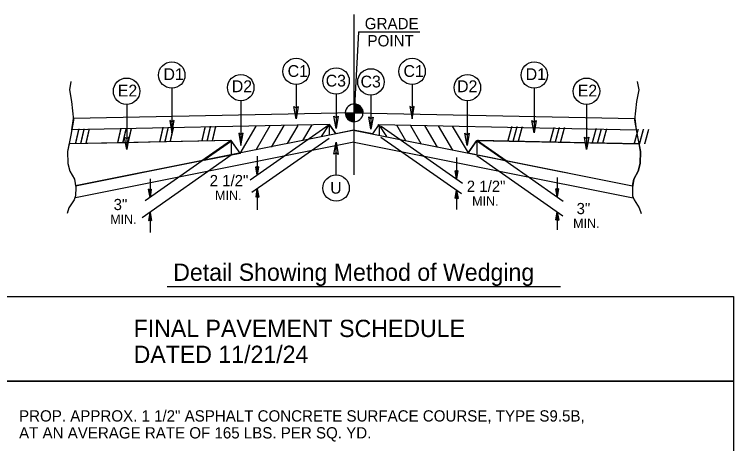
# Model space of a CAD drawing. Extents: x 1901984 to 1902132, y 194049 to 194156.
# Drawn here: x 1902088.64 to 1902130.25, y 194104.06 to 194128.91 of the extents above; entities that cross this region are included whole.
import ezdxf

# ---------------------------------------------------------------- set-up
doc = ezdxf.new("R2010")
doc.units = 0
for name, color, linetype in [('Old_Level_1', 7, 'Continuous'), ('Old_Level_11', 7, 'Continuous'), ('Old_Level_19', 7, 'Continuous'), ('Old_Level_20', 7, 'Continuous'), ('Old_Level_21', 7, 'Continuous'), ('Old_Level_3', 7, 'Continuous')]:
    doc.layers.add(name, color=color, linetype=linetype)

msp = doc.modelspace()

# ---------------------------------------------------------------- linework, layer by layer
at = {"layer": 'Old_Level_1'}
for p, q in [((1902108.298, 194123.202), (1902108.298, 194123.713)), ((1902107.786, 194123.202), (1902108.298, 194123.202)), ((1902108.294, 194122.691), (1902108.294, 194123.196)), ((1902108.298, 194123.202), (1902108.298, 194122.691)), ((1902108.81, 194123.202), (1902108.298, 194123.202)), ((1902108.298, 194122.691), (1902108.298, 194123.202)), ((1902102.612, 194122.439), (1902101.689, 194120.857)), ((1902106.851, 194122.512), (1902102.277, 194119.308)), ((1902103.422, 194122.455), (1902102.605, 194121.053)), ((1902104.224, 194122.471), (1902103.491, 194121.214)), ((1902105.032, 194122.469), (1902104.425, 194121.429)), ((1902105.847, 194122.511), (1902105.317, 194121.603)), ((1902109.855, 194122.437), (1902114.567, 194119.137)), ((1902110.742, 194122.511), (1902111.272, 194121.603)), ((1902111.556, 194122.469), (1902112.164, 194121.429)), ((1902112.365, 194122.471), (1902113.098, 194121.214)), ((1902113.167, 194122.455), (1902113.984, 194121.053)), ((1902113.978, 194122.439), (1902114.886, 194120.881)), ((1902106.862, 194121.729), (1902102.385, 194118.595)), ((1902109.848, 194121.795), (1902114.515, 194118.528)), ((1902101.192, 194121.596), (1902091.808, 194121.408)), ((1902108.288, 194121.51), (1902092.175, 194118.287)), ((1902101.192, 194121.596), (1902096.209, 194118.107)), ((1902101.702, 194120.879), (1902101.192, 194121.596)), ((1902101.192, 194121.596), (1902101.192, 194120.777)), ((1902108.3, 194121.51), (1902124.451, 194118.279)), ((1902114.888, 194120.881), (1902115.397, 194121.596)), ((1902115.397, 194121.596), (1902124.781, 194121.408)), ((1902115.397, 194121.596), (1902115.397, 194120.835)), ((1902115.397, 194121.596), (1902120.387, 194118.102)), ((1902114.886, 194120.881), (1902117.032, 194120.451)), ((1902099.558, 194120.451), (1902092.18, 194118.976)), ((1902101.188, 194120.752), (1902096.037, 194117.127)), ((1902101.192, 194120.779), (1902099.558, 194120.451)), ((1902102.693, 194120.688), (1902102.693, 194119.6)), ((1902114.223, 194120.626), (1902114.223, 194119.378)), ((1902115.397, 194120.736), (1902120.379, 194117.246)), ((1902102.693, 194119.6), (1902102.609, 194120.077)), ((1902102.693, 194120.015), (1902102.609, 194120.077)), ((1902102.693, 194119.6), (1902102.621, 194120.068)), ((1902102.633, 194120.059), (1902102.693, 194119.6)), ((1902102.693, 194119.6), (1902102.645, 194120.051)), ((1902102.658, 194120.042), (1902102.693, 194119.6)), ((1902102.693, 194119.6), (1902102.67, 194120.033)), ((1902102.693, 194119.6), (1902102.778, 194120.077)), ((1902102.778, 194120.077), (1902102.693, 194120.015)), ((1902102.766, 194120.068), (1902102.693, 194119.6)), ((1902102.693, 194119.6), (1902102.753, 194120.059)), ((1902102.741, 194120.051), (1902102.693, 194119.6)), ((1902102.693, 194119.6), (1902102.729, 194120.042)), ((1902102.717, 194120.033), (1902102.693, 194119.6)), ((1902102.682, 194120.024), (1902102.693, 194119.6)), ((1902102.693, 194119.6), (1902102.705, 194120.024)), ((1902102.693, 194120.015), (1902102.693, 194119.6)), ((1902114.223, 194119.378), (1902114.139, 194119.856)), ((1902114.223, 194119.794), (1902114.139, 194119.856)), ((1902114.223, 194119.378), (1902114.151, 194119.847)), ((1902114.163, 194119.838), (1902114.223, 194119.378)), ((1902114.223, 194119.378), (1902114.175, 194119.829)), ((1902114.187, 194119.82), (1902114.223, 194119.378)), ((1902114.223, 194119.378), (1902114.199, 194119.812)), ((1902114.211, 194119.803), (1902114.223, 194119.378)), ((1902114.223, 194119.378), (1902114.308, 194119.856)), ((1902114.308, 194119.856), (1902114.223, 194119.794)), ((1902114.295, 194119.847), (1902114.223, 194119.378)), ((1902114.223, 194119.378), (1902114.283, 194119.838)), ((1902114.271, 194119.829), (1902114.223, 194119.378)), ((1902114.223, 194119.378), (1902114.259, 194119.82)), ((1902114.247, 194119.812), (1902114.223, 194119.378)), ((1902114.223, 194119.378), (1902114.236, 194119.803)), ((1902114.223, 194119.794), (1902114.223, 194119.378)), ((1902096.49, 194119.388), (1902096.49, 194118.303)), ((1902120.049, 194119.467), (1902120.049, 194118.339)), ((1902102.693, 194118.81), (1902102.609, 194118.333)), ((1902102.621, 194118.342), (1902102.693, 194118.81)), ((1902102.693, 194118.81), (1902102.633, 194118.35)), ((1902102.645, 194118.36), (1902102.693, 194118.81)), ((1902102.693, 194118.81), (1902102.658, 194118.368)), ((1902102.67, 194118.377), (1902102.693, 194118.81)), ((1902102.693, 194118.81), (1902102.682, 194118.386)), ((1902102.693, 194118.81), (1902102.693, 194117.585)), ((1902102.693, 194118.81), (1902102.778, 194118.333)), ((1902102.693, 194118.395), (1902102.693, 194118.81)), ((1902102.705, 194118.386), (1902102.693, 194118.81)), ((1902102.693, 194118.81), (1902102.717, 194118.377)), ((1902102.729, 194118.368), (1902102.693, 194118.81)), ((1902102.693, 194118.81), (1902102.741, 194118.36)), ((1902102.753, 194118.35), (1902102.693, 194118.81)), ((1902102.693, 194118.81), (1902102.766, 194118.342)), ((1902120.049, 194118.339), (1902119.965, 194118.816)), ((1902120.049, 194118.754), (1902119.965, 194118.816)), ((1902120.049, 194118.339), (1902119.977, 194118.807)), ((1902119.989, 194118.798), (1902120.049, 194118.339)), ((1902120.049, 194118.339), (1902120.001, 194118.79)), ((1902120.049, 194118.339), (1902120.133, 194118.816)), ((1902120.133, 194118.816), (1902120.049, 194118.754)), ((1902120.121, 194118.807), (1902120.049, 194118.339)), ((1902120.049, 194118.339), (1902120.109, 194118.798)), ((1902120.097, 194118.79), (1902120.049, 194118.339)), ((1902096.49, 194118.303), (1902096.405, 194118.78)), ((1902096.49, 194118.719), (1902096.405, 194118.78)), ((1902096.49, 194118.303), (1902096.417, 194118.772)), ((1902096.43, 194118.762), (1902096.49, 194118.303)), ((1902096.49, 194118.303), (1902096.442, 194118.754)), ((1902096.454, 194118.745), (1902096.49, 194118.303)), ((1902096.49, 194118.303), (1902096.466, 194118.737)), ((1902096.478, 194118.728), (1902096.49, 194118.303)), ((1902096.49, 194118.303), (1902096.574, 194118.78)), ((1902096.574, 194118.78), (1902096.49, 194118.719)), ((1902096.562, 194118.772), (1902096.49, 194118.303)), ((1902096.49, 194118.303), (1902096.55, 194118.762)), ((1902096.538, 194118.754), (1902096.49, 194118.303)), ((1902096.49, 194118.303), (1902096.525, 194118.745)), ((1902096.514, 194118.737), (1902096.49, 194118.303)), ((1902096.49, 194118.303), (1902096.502, 194118.728)), ((1902096.49, 194118.719), (1902096.49, 194118.303)), ((1902102.609, 194118.333), (1902102.693, 194118.395)), ((1902102.693, 194118.395), (1902102.778, 194118.333)), ((1902114.223, 194118.732), (1902114.139, 194118.255)), ((1902114.151, 194118.265), (1902114.223, 194118.732)), ((1902114.223, 194118.732), (1902114.163, 194118.273)), ((1902114.175, 194118.282), (1902114.223, 194118.732)), ((1902114.223, 194118.732), (1902114.187, 194118.291)), ((1902114.199, 194118.299), (1902114.223, 194118.732)), ((1902114.223, 194118.732), (1902114.211, 194118.308)), ((1902114.223, 194118.732), (1902114.223, 194117.616)), ((1902114.223, 194118.732), (1902114.308, 194118.255)), ((1902114.223, 194118.317), (1902114.223, 194118.732)), ((1902114.236, 194118.308), (1902114.223, 194118.732)), ((1902114.223, 194118.732), (1902114.247, 194118.299)), ((1902114.259, 194118.291), (1902114.223, 194118.732)), ((1902114.223, 194118.732), (1902114.271, 194118.282)), ((1902114.283, 194118.273), (1902114.223, 194118.732)), ((1902114.223, 194118.732), (1902114.295, 194118.265)), ((1902120.013, 194118.78), (1902120.049, 194118.339)), ((1902120.049, 194118.339), (1902120.025, 194118.772)), ((1902120.037, 194118.762), (1902120.049, 194118.339)), ((1902120.049, 194118.339), (1902120.085, 194118.78)), ((1902120.073, 194118.772), (1902120.049, 194118.339)), ((1902120.049, 194118.339), (1902120.061, 194118.762)), ((1902120.049, 194118.754), (1902120.049, 194118.339)), ((1902114.139, 194118.255), (1902114.223, 194118.317)), ((1902114.223, 194118.317), (1902114.308, 194118.255)), ((1902096.49, 194117.445), (1902096.405, 194116.967)), ((1902096.418, 194116.976), (1902096.49, 194117.445)), ((1902096.49, 194117.445), (1902096.43, 194116.985)), ((1902096.442, 194116.994), (1902096.49, 194117.445)), ((1902096.49, 194117.445), (1902096.454, 194117.003)), ((1902096.466, 194117.011), (1902096.49, 194117.445)), ((1902096.49, 194117.445), (1902096.478, 194117.02)), ((1902096.49, 194117.445), (1902096.49, 194116.284)), ((1902096.49, 194117.445), (1902096.574, 194116.967)), ((1902096.49, 194117.029), (1902096.49, 194117.445)), ((1902096.502, 194117.02), (1902096.49, 194117.445)), ((1902096.49, 194117.445), (1902096.514, 194117.011)), ((1902096.526, 194117.003), (1902096.49, 194117.445)), ((1902096.49, 194117.445), (1902096.538, 194116.994)), ((1902096.55, 194116.985), (1902096.49, 194117.445)), ((1902096.49, 194117.445), (1902096.562, 194116.976)), ((1902120.049, 194117.478), (1902119.965, 194117)), ((1902119.977, 194117.009), (1902120.049, 194117.478)), ((1902120.049, 194117.478), (1902119.989, 194117.018)), ((1902120.001, 194117.027), (1902120.049, 194117.478)), ((1902120.049, 194117.478), (1902120.013, 194117.036)), ((1902120.025, 194117.045), (1902120.049, 194117.478)), ((1902120.049, 194117.478), (1902120.037, 194117.053)), ((1902120.049, 194117.478), (1902120.049, 194116.43)), ((1902120.049, 194117.478), (1902120.133, 194117)), ((1902120.049, 194117.063), (1902120.049, 194117.478)), ((1902120.061, 194117.053), (1902120.049, 194117.478)), ((1902120.049, 194117.478), (1902120.073, 194117.045)), ((1902120.085, 194117.036), (1902120.049, 194117.478)), ((1902120.049, 194117.478), (1902120.097, 194117.027)), ((1902120.109, 194117.018), (1902120.049, 194117.478)), ((1902120.049, 194117.478), (1902120.121, 194117.009)), ((1902096.405, 194116.967), (1902096.49, 194117.029)), ((1902096.49, 194117.029), (1902096.574, 194116.967)), ((1902119.965, 194117), (1902120.049, 194117.063)), ((1902120.049, 194117.063), (1902120.133, 194117))]:
    msp.add_line(p, q, dxfattribs=at)
for points in [[(1902091.907, 194125.021), (1902091.821, 194124.545), (1902091.951, 194123.869), (1902092.066, 194122.775), (1902091.907, 194121.91), (1902091.72, 194120.974), (1902091.735, 194120.268), (1902091.85, 194119.822), (1902092.11, 194119.375), (1902092.196, 194118.886), (1902092.181, 194118.396), (1902092.095, 194118.165), (1902091.793, 194117.705), (1902091.692, 194117.388)], [(1902124.681, 194125.021), (1902124.768, 194124.545), (1902124.638, 194123.869), (1902124.523, 194122.775), (1902124.681, 194121.91), (1902124.869, 194120.974), (1902124.854, 194120.268), (1902124.739, 194119.822), (1902124.479, 194119.375), (1902124.394, 194118.886), (1902124.407, 194118.396), (1902124.494, 194118.165), (1902124.796, 194117.705), (1902124.897, 194117.388)], [(1902108.302, 194123.713), (1902108.302, 194123.713), (1902108.302, 194123.202)], [(1902108.313, 194123.713), (1902108.313, 194123.202)], [(1902108.323, 194123.713), (1902108.323, 194123.202)], [(1902108.333, 194123.713), (1902108.333, 194123.202)], [(1902108.344, 194123.712), (1902108.344, 194123.202)], [(1902108.354, 194123.71), (1902108.354, 194123.202)], [(1902108.365, 194123.71), (1902108.365, 194123.202)], [(1902108.374, 194123.708), (1902108.374, 194123.202)], [(1902108.384, 194123.706), (1902108.384, 194123.202)], [(1902108.395, 194123.704), (1902108.395, 194123.202)], [(1902108.405, 194123.703), (1902108.405, 194123.202)], [(1902108.416, 194123.7), (1902108.416, 194123.202)], [(1902108.426, 194123.698), (1902108.426, 194123.202)], [(1902108.436, 194123.695), (1902108.436, 194123.202)], [(1902108.445, 194123.692), (1902108.445, 194123.202)], [(1902108.456, 194123.689), (1902108.456, 194123.202)], [(1902108.466, 194123.685), (1902108.466, 194123.202)], [(1902108.477, 194123.682), (1902108.477, 194123.202)], [(1902108.487, 194123.677), (1902108.487, 194123.202)], [(1902108.498, 194123.673), (1902108.497, 194123.202)], [(1902108.508, 194123.669), (1902108.508, 194123.202)], [(1902108.517, 194123.664), (1902108.517, 194123.202)], [(1902108.527, 194123.659), (1902108.527, 194123.202)], [(1902108.538, 194123.654), (1902108.538, 194123.202)], [(1902108.548, 194123.648), (1902108.548, 194123.202)], [(1902108.559, 194123.642), (1902108.559, 194123.202)], [(1902108.569, 194123.636), (1902108.569, 194123.202)], [(1902108.579, 194123.63), (1902108.579, 194123.202)], [(1902108.589, 194123.623), (1902108.589, 194123.202)], [(1902108.599, 194123.615), (1902108.599, 194123.202)], [(1902108.61, 194123.608), (1902108.61, 194123.202)], [(1902108.62, 194123.6), (1902108.62, 194123.202)], [(1902108.631, 194123.591), (1902108.631, 194123.202)], [(1902108.641, 194123.582), (1902108.64, 194123.202)], [(1902108.651, 194123.572), (1902108.651, 194123.202)], [(1902108.66, 194123.563), (1902108.66, 194123.202)], [(1902108.671, 194123.552), (1902108.671, 194123.202)], [(1902108.681, 194123.54), (1902108.681, 194123.202)], [(1902108.691, 194123.528), (1902108.691, 194123.202)], [(1902108.702, 194123.516), (1902108.702, 194123.202)], [(1902108.712, 194123.503), (1902108.712, 194123.202)], [(1902108.722, 194123.488), (1902108.722, 194123.202)], [(1902108.732, 194123.472), (1902108.732, 194123.202)], [(1902108.742, 194123.455), (1902108.742, 194123.202)], [(1902108.753, 194123.436), (1902108.753, 194123.202)], [(1902108.763, 194123.414), (1902108.763, 194123.202)], [(1902108.774, 194123.391), (1902108.774, 194123.202)], [(1902108.783, 194123.362), (1902108.783, 194123.202)], [(1902107.789, 194123.202), (1902107.789, 194123.146)], [(1902107.799, 194123.202), (1902107.799, 194123.087)], [(1902107.81, 194123.202), (1902107.81, 194123.05)], [(1902107.82, 194123.202), (1902107.82, 194123.02)], [(1902107.83, 194123.202), (1902107.83, 194122.994)], [(1902107.84, 194123.202), (1902107.84, 194122.973)], [(1902107.85, 194123.202), (1902107.85, 194122.954)], [(1902107.861, 194123.202), (1902107.861, 194122.936)], [(1902107.871, 194123.202), (1902107.871, 194122.92)], [(1902107.882, 194123.202), (1902107.882, 194122.905)], [(1902107.892, 194123.202), (1902107.892, 194122.891)], [(1902107.902, 194123.202), (1902107.902, 194122.878)], [(1902107.912, 194123.202), (1902107.912, 194122.866)], [(1902107.922, 194123.202), (1902107.922, 194122.855)], [(1902107.932, 194123.202), (1902107.932, 194122.844)], [(1902107.942, 194123.202), (1902107.942, 194122.835)], [(1902107.953, 194123.202), (1902107.953, 194122.824)], [(1902107.963, 194123.202), (1902107.963, 194122.815)], [(1902107.973, 194123.202), (1902107.973, 194122.806)], [(1902107.983, 194123.202), (1902107.983, 194122.799)], [(1902107.993, 194123.202), (1902107.993, 194122.791)], [(1902108.004, 194123.202), (1902108.004, 194122.784)], [(1902108.014, 194123.202), (1902108.014, 194122.776)], [(1902108.025, 194123.202), (1902108.025, 194122.77)], [(1902108.035, 194123.202), (1902108.034, 194122.763)], [(1902108.045, 194123.202), (1902108.045, 194122.757)], [(1902108.055, 194123.202), (1902108.055, 194122.752)], [(1902108.065, 194123.202), (1902108.065, 194122.746)], [(1902108.075, 194123.202), (1902108.075, 194122.741)], [(1902108.086, 194123.202), (1902108.086, 194122.737)], [(1902108.097, 194123.202), (1902108.097, 194122.732)], [(1902108.107, 194123.202), (1902108.106, 194122.728)], [(1902108.116, 194123.202), (1902108.116, 194122.724)], [(1902108.127, 194123.202), (1902108.127, 194122.72)], [(1902108.136, 194123.202), (1902108.136, 194122.717)], [(1902108.147, 194123.202), (1902108.147, 194122.714)], [(1902108.157, 194123.202), (1902108.157, 194122.711)], [(1902108.168, 194123.202), (1902108.168, 194122.708)], [(1902108.178, 194123.202), (1902108.178, 194122.705)], [(1902108.188, 194123.202), (1902108.188, 194122.703)], [(1902108.199, 194123.202), (1902108.198, 194122.701)], [(1902108.208, 194123.202), (1902108.208, 194122.699)], [(1902108.219, 194123.202), (1902108.219, 194122.697)], [(1902108.229, 194123.202), (1902108.229, 194122.695)], [(1902108.24, 194123.202), (1902108.24, 194122.695)], [(1902108.25, 194123.202), (1902108.249, 194122.693)], [(1902108.259, 194123.202), (1902108.259, 194122.692)], [(1902108.27, 194123.202), (1902108.27, 194122.691)], [(1902108.28, 194123.202), (1902108.28, 194122.691)], [(1902108.291, 194123.202), (1902108.291, 194122.691), (1902108.291, 194122.691)], [(1902108.794, 194123.327), (1902108.794, 194123.202)], [(1902108.804, 194123.275), (1902108.804, 194123.202)]]:
    msp.add_lwpolyline(points, dxfattribs=at)
for start, end in [(358.0003, 356.1713), (359.9905, 89.9905), (179.9905, 268.7186), (269.6533, 269.9905)]:
    msp.add_arc((1902108.298, 194123.202), 0.512, start, end, dxfattribs=at)
at = {"layer": 'Old_Level_11'}
for p, q in [((1902108.294, 194119.622), (1902108.294, 194128.905)), ((1902097.759, 194124.63), (1902097.759, 194122.048)), ((1902104.938, 194124.842), (1902104.938, 194122.864)), ((1902111.65, 194124.842), (1902111.65, 194122.864)), ((1902118.708, 194124.63), (1902118.708, 194122.048)), ((1902107.252, 194124.285), (1902107.252, 194122.307)), ((1902109.269, 194124.232), (1902109.269, 194122.254)), ((1902101.751, 194123.9), (1902101.751, 194121.319)), ((1902114.837, 194123.9), (1902114.837, 194121.319)), ((1902095.139, 194123.688), (1902095.139, 194121.093)), ((1902121.748, 194123.688), (1902121.748, 194121.093)), ((1902108.294, 194123.202), (1902092.059, 194122.878)), ((1902108.294, 194123.202), (1902124.531, 194122.878)), ((1902108.296, 194123.202), (1902124.531, 194122.878)), ((1902091.966, 194122.226), (1902092.059, 194122.878)), ((1902124.531, 194122.878), (1902124.624, 194122.226)), ((1902106.87, 194122.524), (1902091.966, 194122.226)), ((1902108.319, 194122.205), (1902092.18, 194118.976)), ((1902106.408, 194121.83), (1902106.849, 194122.518)), ((1902106.849, 194122.518), (1902106.849, 194121.952)), ((1902107.234, 194121.989), (1902106.87, 194122.524)), ((1902106.87, 194122.506), (1902107.234, 194121.989)), ((1902108.27, 194122.205), (1902107.234, 194121.989)), ((1902108.27, 194122.205), (1902124.409, 194118.976)), ((1902109.354, 194121.989), (1902108.27, 194122.205)), ((1902109.731, 194122.524), (1902109.354, 194121.989)), ((1902109.667, 194122.503), (1902109.689, 194122.502)), ((1902109.707, 194122.512), (1902109.73, 194122.511)), ((1902109.731, 194122.524), (1902124.624, 194122.226)), ((1902110.181, 194121.83), (1902109.74, 194122.518)), ((1902109.74, 194122.518), (1902109.74, 194121.894)), ((1902091.808, 194121.408), (1902091.72, 194120.974)), ((1902095.072, 194121.474), (1902091.808, 194121.408)), ((1902101.146, 194121.595), (1902096.395, 194121.5)), ((1902099.493, 194120.438), (1902101.146, 194121.595)), ((1902107.256, 194119.62), (1902107.256, 194121.513)), ((1902115.499, 194121.595), (1902115.443, 194121.595)), ((1902115.443, 194121.595), (1902117.093, 194120.44)), ((1902121.682, 194121.47), (1902115.499, 194121.595)), ((1902124.781, 194121.408), (1902121.813, 194121.467)), ((1902092.18, 194118.976), (1902099.493, 194120.438)), ((1902117.093, 194120.44), (1902117.093, 194120.44)), ((1902117.093, 194120.44), (1902117.093, 194120.44)), ((1902117.093, 194120.44), (1902117.093, 194120.44)), ((1902117.093, 194120.44), (1902117.093, 194120.44)), ((1902117.093, 194120.44), (1902117.093, 194120.44)), ((1902117.093, 194120.44), (1902117.093, 194120.44)), ((1902117.093, 194120.44), (1902124.409, 194118.976)), ((1902124.41, 194118.976), (1902124.479, 194119.375)), ((1902124.409, 194118.976), (1902124.41, 194118.976)), ((1902097.479, 194113.156), (1902120.236, 194113.156))]:
    msp.add_line(p, q, dxfattribs=at)
for points in [[(1902105.06, 194123.572), (1902104.938, 194122.864), (1902104.812, 194123.576), (1902104.938, 194123.486)], [(1902111.528, 194123.572), (1902111.65, 194122.864), (1902111.776, 194123.576), (1902111.65, 194123.486)], [(1902107.374, 194123.016), (1902107.252, 194122.307), (1902107.126, 194123.02), (1902107.252, 194122.929)], [(1902109.391, 194122.962), (1902109.269, 194122.254), (1902109.143, 194122.966), (1902109.269, 194122.876)], [(1902097.637, 194122.757), (1902097.759, 194122.048), (1902097.885, 194122.761), (1902097.759, 194122.67)], [(1902118.83, 194122.757), (1902118.708, 194122.048), (1902118.582, 194122.761), (1902118.708, 194122.67)], [(1902095.261, 194121.802), (1902095.139, 194121.093), (1902095.013, 194121.805), (1902095.139, 194121.715)], [(1902101.629, 194122.028), (1902101.751, 194121.319), (1902101.877, 194122.031), (1902101.751, 194121.941)], [(1902114.959, 194122.028), (1902114.837, 194121.319), (1902114.711, 194122.031), (1902114.837, 194121.941)], [(1902121.87, 194121.802), (1902121.748, 194121.093), (1902121.622, 194121.805), (1902121.748, 194121.715)], [(1902101.702, 194120.879), (1902101.206, 194121.575), (1902099.62, 194120.464)], [(1902107.133, 194120.804), (1902107.256, 194121.513), (1902107.382, 194120.801), (1902107.256, 194120.891)], [(1902115.382, 194121.576), (1902114.888, 194120.881), (1902116.969, 194120.464)]]:
    msp.add_lwpolyline(points, close=True, dxfattribs=at)
for points in [[(1902096.395, 194121.5), (1902095.205, 194121.476), (1902095.139, 194121.093), (1902095.072, 194121.474)], [(1902121.813, 194121.467), (1902121.748, 194121.093), (1902121.682, 194121.47)], [(1902124.479, 194119.375), (1902124.739, 194119.822), (1902124.854, 194120.268), (1902124.869, 194120.974), (1902124.781, 194121.408)], [(1902091.72, 194120.974), (1902091.735, 194120.268), (1902091.85, 194119.822)], [(1902091.85, 194119.822), (1902092.11, 194119.375), (1902092.18, 194118.976)]]:
    msp.add_lwpolyline(points, dxfattribs=at)
for centre in [(1902104.938, 194125.607), (1902111.65, 194125.607), (1902097.745, 194125.395), (1902118.722, 194125.395), (1902107.252, 194125.051), (1902109.269, 194124.997), (1902095.131, 194124.454), (1902101.737, 194124.665), (1902114.851, 194124.665), (1902121.741, 194124.454), (1902107.255, 194118.854)]:
    msp.add_circle(centre, 0.765, dxfattribs=at)
at = {"layer": 'Old_Level_19'}
msp.add_lwpolyline([(1902082.253, 194112.582), (1902130.254, 194112.582), (1902130.254, 194107.673), (1902082.253, 194107.673)], close=True, dxfattribs=at)
msp.add_lwpolyline([(1902087.162, 194102.764), (1902082.253, 194102.764), (1902082.253, 194107.673), (1902130.253, 194107.673), (1902130.253, 194102.764), (1902087.162, 194102.764), (1902087.162, 194107.673)], dxfattribs=at)
at = {"layer": 'Old_Level_3'}
for q in [(1902108.296, 194123.202), (1902112.103, 194127.886)]:
    msp.add_line((1902108.546, 194127.886), q, dxfattribs=at)

# ---------------------------------------------------------------- texts
at = {"layer": 'Old_Level_1'}
for height, rotation, p in [(0.8142, 1.1447, (1902092.131, 194121.42)), (0.8142, 1.1464, (1902094.565, 194121.449)), (0.8139, 1.1445, (1902097.003, 194121.52)), (0.8139, 1.1463, (1902099.444, 194121.57)), (0.8139, 358.8553, (1902117.145, 194121.57)), (0.8139, 358.8536, (1902119.587, 194121.52)), (0.8142, 358.8554, (1902122.025, 194121.449)), (0.8142, 358.8537, (1902124.458, 194121.42))]:
    msp.add_text('/// ', height=height, rotation=rotation, dxfattribs=at).set_placement(p)
at = {"layer": 'Old_Level_11'}
for s, p in [('GRADE', (1902108.912, 194128.044)), ('POINT', (1902109.07, 194127.05))]:
    msp.add_text(s, height=0.656, dxfattribs=at).set_placement(p)
at = {"layer": 'Old_Level_20'}
for s, height, p in [('C1', 0.6851, (1902104.451, 194125.284)), ('C1', 0.6851, (1902111.155, 194125.284)), ('D1', 0.6851, (1902097.269, 194125.101)), ('D1', 0.6851, (1902118.225, 194125.101)), ('D2', 0.6851, (1902101.222, 194124.401)), ('C3', 0.6851, (1902106.654, 194124.727)), ('C3', 0.6851, (1902108.671, 194124.674)), ('D2', 0.6851, (1902114.255, 194124.401)), ('E2', 0.6851, (1902094.628, 194124.152)), ('E2', 0.6851, (1902121.237, 194124.152)), ('2 1/2"', 0.6491, (1902099.94, 194118.96)), ('U', 0.685, (1902106.913, 194118.525)), ('2 1/2"', 0.6491, (1902114.814, 194118.629)), ('3"', 0.6491, (1902094.382, 194117.575)), ('3"', 0.6491, (1902121.167, 194117.34))]:
    msp.add_text(s, height=height, dxfattribs=at).set_placement(p)
at = {"layer": 'Old_Level_21'}
for s, height, p in [('MIN.', 0.5424, (1902100.252, 194118.162)), ('MIN.', 0.5424, (1902115.125, 194117.831)), ('MIN.', 0.5424, (1902094.183, 194116.777)), ('MIN.', 0.5424, (1902120.968, 194116.542)), ('Detail Showing Method of Wedging', 1, (1902097.83, 194113.48)), ('FINAL PAVEMENT SCHEDULE', 1, (1902095.54, 194110.227)), ('DATED 11/21/24', 1, (1902095.54, 194108.727)), ('PROP. APPROX. 1 1/2" ASPHALT CONCRETE SURFACE COURSE, TYPE S9.5B,', 0.653, (1902088.912, 194105.335)), ('AT AN AVERAGE RATE OF 165 LBS. PER SQ. YD.', 0.653, (1902088.912, 194104.356))]:
    msp.add_text(s, height=height, dxfattribs=at).set_placement(p)

doc.saveas('drawing.dxf')
